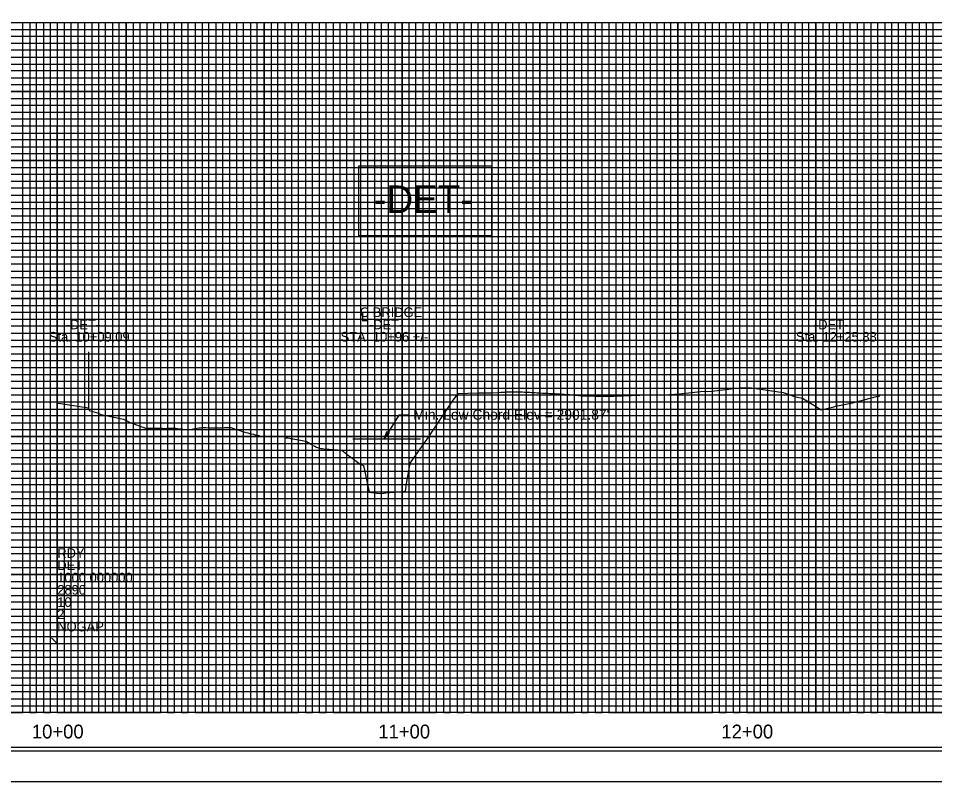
# Model space of a CAD drawing. Extents: x 1191114 to 1192543, y 893004 to 894332.
# Drawn here: x 1191281.1 to 1191546.9, y 893892.3 to 894113.5 of the extents above; entities that cross this region are included whole.
import ezdxf

# ---------------------------------------------------------------- set-up
doc = ezdxf.new("R2010")
doc.units = 0
for name, color, linetype in [('Exist Profile Cell', 7, 'Continuous'), ('Exist Vertical Profile Ground Line', 7, 'Continuous'), ('Prop Grid Mask', 7, 'Continuous'), ('Prop PFL Text', 7, 'Continuous'), ('Prop Vertical Profile Curve Label', 7, 'Continuous'), ('Prop VPI Ditch Grade Right Label', 7, 'Continuous'), ('Sheet Cutting Line CELL', 7, 'Continuous'), ('Sheet DOT Grid CELL', 7, 'Continuous'), ('Sheet Layout Profile Border Port 2', 7, 'Continuous'), ('Sheet Plot Border Inside CELL', 7, 'Continuous'), ('Sheet Plot Border Outside CELL', 7, 'Continuous'), ('Sheet Profile CELL', 7, 'Continuous'), ('Sheet Profile Grid Major CELL', 7, 'Continuous'), ('Sheet Profile Grid Middle CELL', 7, 'Continuous'), ('Sheet Profile Grid Minor CELL', 7, 'Continuous'), ('Typical Terminator CELL', 7, 'Continuous')]:
    doc.layers.add(name, color=color, linetype=linetype)

# ---------------------------------------------------------------- blocks, each defined once
blk = doc.blocks.new('TERMINATOR')
at = {"layer": 'Typical Terminator CELL'}
blk.add_lwpolyline([(-0.469, 0.081), (0, 0), (-0.471, -0.083), (-0.411, 0)], close=True, dxfattribs=at)

msp = doc.modelspace()

# ---------------------------------------------------------------- linework, layer by layer
at = {"layer": 'Exist Profile Cell'}
for q in [(1191292.39, 894082.3), (1191530.97, 893932.3), (1191292.39, 893932.3)]:
    msp.add_line((1191292.39, 893932.3), q, dxfattribs=at)
at = {"layer": 'Exist Vertical Profile Ground Line'}
msp.add_lwpolyline([(1191292.39, 894002.02), (1191293.45, 894001.89), (1191301.48, 894000.69), (1191301.67, 893999.83), (1191304.34, 893999.08), (1191305.07, 893998.7), (1191306.46, 893998.45), (1191311.62, 893997.41), (1191313.53, 893996.39), (1191318, 893994.72), (1191323.03, 893994.72), (1191324.07, 893994.69), (1191324.6, 893994.72), (1191325.12, 893994.74), (1191325.65, 893994.76), (1191326, 893994.78), (1191326.7, 893994.71), (1191327.22, 893994.65), (1191327.75, 893994.6), (1191328.27, 893994.54), (1191328.8, 893994.48), (1191329.32, 893994.41), (1191329.85, 893994.35), (1191330.45, 893994.28), (1191330.9, 893994.36), (1191331.42, 893994.45), (1191331.94, 893994.55), (1191332.47, 893994.64), (1191332.99, 893994.73), (1191333.52, 893994.81), (1191334.04, 893994.89), (1191334.57, 893994.91), (1191335.09, 893994.92), (1191335.48, 893994.93), (1191336.27, 893994.88), (1191336.67, 893994.88), (1191337.19, 893994.88), (1191337.72, 893994.88), (1191338.24, 893994.88), (1191338.77, 893994.88), (1191339.29, 893994.89), (1191339.81, 893994.89), (1191340.34, 893994.89), (1191340.86, 893994.9), (1191341.39, 893994.9), (1191341.91, 893994.9), (1191342.72, 893994.91), (1191343.49, 893994.66), (1191344.01, 893994.49), (1191344.54, 893994.32), (1191345.06, 893994.15), (1191345.59, 893993.99), (1191346.11, 893993.83), (1191346.81, 893993.62), (1191347.16, 893993.52), (1191347.68, 893993.38), (1191348.21, 893993.24), (1191348.73, 893993.11), (1191349.26, 893992.97), (1191349.78, 893992.84), (1191350.31, 893992.71), (1191350.83, 893992.59), (1191351.36, 893992.46), (1191351.71, 893992.38), (1191352.41, 893992.41), (1191352.93, 893992.43), (1191353.57, 893992.45), (1191353.98, 893992.43), (1191354.51, 893992.41), (1191355.03, 893992.39), (1191355.55, 893992.37), (1191356.08, 893992.34), (1191356.6, 893992.32), (1191357.24, 893992.3), (1191357.65, 893992.39), (1191358.18, 893992.39), (1191358.9, 893991.98), (1191359.23, 893991.91), (1191359.75, 893991.81), (1191360.28, 893991.71), (1191360.8, 893991.62), (1191361.33, 893991.52), (1191361.85, 893991.43), (1191362.38, 893991.34), (1191362.9, 893991.25), (1191363.42, 893991.17), (1191363.95, 893991.09), (1191364.56, 893991), (1191365, 893990.72), (1191365.52, 893990.4), (1191366.05, 893990.07), (1191366.61, 893989.73), (1191367.1, 893989.5), (1191367.62, 893989.25), (1191368.15, 893989.04), (1191368.8, 893988.86), (1191369.2, 893988.82), (1191369.72, 893988.76), (1191370.25, 893988.71), (1191370.77, 893988.67), (1191371.29, 893988.63), (1191374.96, 893988.34), (1191376.86, 893986.84), (1191377.41, 893986.48), (1191380.29, 893984.35), (1191381.2, 893983.93), (1191382.87, 893976.17), (1191385.01, 893975.94), (1191386.56, 893975.85), (1191387.64, 893976.03), (1191393.39, 893976.54), (1191393.73, 893978.66), (1191394.73, 893984.58), (1191399.68, 893991.52), (1191407.05, 894002.61), (1191408.65, 894004.79), (1191414.31, 894004.99), (1191418.51, 894005.01), (1191420.2, 894005.1), (1191421.06, 894005.16), (1191421.58, 894005.19), (1191422.1, 894005.23), (1191422.63, 894005.26), (1191423.15, 894005.26), (1191423.67, 894005.26), (1191424.2, 894005.26), (1191424.72, 894005.26), (1191425.24, 894005.26), (1191425.77, 894005.26), (1191426.29, 894005.26), (1191426.81, 894005.26), (1191427.34, 894005.24), (1191427.86, 894005.21), (1191428.38, 894005.19), (1191428.91, 894005.17), (1191429.43, 894005.14), (1191429.95, 894005.11), (1191430.48, 894005.09), (1191431, 894005.06), (1191431.52, 894005.03), (1191432.05, 894005), (1191432.57, 894004.97), (1191433.09, 894004.94), (1191433.62, 894004.91), (1191434.14, 894004.88), (1191434.66, 894004.85), (1191435.19, 894004.82), (1191435.71, 894004.79), (1191436.23, 894004.78), (1191436.76, 894004.76), (1191437.28, 894004.74), (1191437.8, 894004.72), (1191438.33, 894004.68), (1191438.85, 894004.64), (1191439.37, 894004.6), (1191439.9, 894004.55), (1191440.42, 894004.51), (1191440.94, 894004.47), (1191441.47, 894004.42), (1191441.99, 894004.37), (1191442.51, 894004.33), (1191443.04, 894004.28), (1191443.56, 894004.23), (1191444.08, 894004.18), (1191444.61, 894004.13), (1191445.13, 894004.12), (1191445.65, 894004.11), (1191446.18, 894004.11), (1191446.7, 894004.1), (1191447.22, 894004.09), (1191447.75, 894004.08), (1191448.27, 894004.07), (1191451.75, 894003.99), (1191452.85, 894004.03), (1191453.85, 894004.03), (1191461.4, 894004.28), (1191462.86, 894004.37), (1191469.92, 894004.48), (1191472.86, 894004.73), (1191478.98, 894005.35), (1191482.23, 894005.52), (1191490.29, 894006.42), (1191492.08, 894006.51), (1191493.75, 894006.45), (1191502.91, 894005.07), (1191506.54, 894003.82), (1191508.55, 894003.41), (1191512.58, 894000.95), (1191513.9, 894000.04), (1191517.58, 894000.97), (1191518.22, 894001.15), (1191522.99, 894002.06), (1191529.97, 894003.92), (1191530.97, 894004.1)], dxfattribs=at)
at = {"layer": 'Prop Grid Mask'}
msp.add_line((1191292.39, 893932.3), (1191290.73, 893933.97), dxfattribs=at)
msp.add_lwpolyline([(1191379.87, 894070.74), (1191418.35, 894070.74), (1191418.35, 894050.54), (1191379.87, 894050.54)], close=True, dxfattribs=at)
at = {"layer": 'Prop PFL Text'}
for p, q in [((1191391.48, 893998.52), (1191387.16, 893991.65)), ((1191394.4, 893998.52), (1191391.48, 893998.52))]:
    msp.add_line(p, q, dxfattribs=at)
at = {"layer": 'Prop VPI Ditch Grade Right Label'}
for p, q in [((1191301.48, 894016.85), (1191301.48, 894000.69)), ((1191388.39, 894004.75), (1191388.39, 894016.85)), ((1191518.27, 894016.85), (1191518.27, 894001.16)), ((1191378.11, 893991.65), (1191397.79, 893991.65))]:
    msp.add_line(p, q, dxfattribs=at)
at = {"layer": 'Sheet Cutting Line CELL'}
msp.add_line((1191165.59, 893892.3), (1191839.19, 893892.3), dxfattribs=at)
at = {"layer": 'Sheet DOT Grid CELL'}
for p, q in [((1191232.39, 894112.3), (1191832.34, 894112.3)), ((1191292.39, 894112.3), (1191292.39, 893912.3)), ((1191312.39, 894112.3), (1191312.39, 893912.3)), ((1191332.39, 894112.3), (1191332.39, 893912.3)), ((1191352.39, 894112.3), (1191352.39, 893912.3)), ((1191372.39, 894112.3), (1191372.39, 893912.3)), ((1191392.39, 894112.3), (1191392.39, 893912.3)), ((1191412.39, 894112.3), (1191412.39, 893912.3)), ((1191432.39, 894112.3), (1191432.39, 893912.3)), ((1191452.39, 894112.3), (1191452.39, 893912.3)), ((1191472.39, 894112.3), (1191472.39, 893912.3)), ((1191492.39, 894112.3), (1191492.39, 893912.3)), ((1191512.39, 894112.3), (1191512.39, 893912.3)), ((1191532.39, 894112.3), (1191532.39, 893912.3)), ((1191232.39, 894092.3), (1191832.34, 894092.3)), ((1191232.39, 894072.3), (1191832.34, 894072.3)), ((1191232.39, 894052.3), (1191832.34, 894052.3)), ((1191232.39, 894032.3), (1191832.34, 894032.3)), ((1191232.39, 894012.3), (1191832.34, 894012.3)), ((1191232.39, 893992.3), (1191832.34, 893992.3)), ((1191232.39, 893972.3), (1191832.34, 893972.3)), ((1191232.39, 893952.3), (1191832.34, 893952.3)), ((1191232.39, 893932.3), (1191832.34, 893932.3))]:
    msp.add_line(p, q, dxfattribs=at)
at = {"layer": 'Sheet Layout Profile Border Port 2'}
msp.add_lwpolyline([(1191252.39, 894112.3), (1191812.39, 894112.3), (1191812.39, 893912.3), (1191252.39, 893912.3)], close=True, dxfattribs=at)
at = {"layer": 'Sheet Plot Border Inside CELL'}
msp.add_lwpolyline([(1191170.79, 893901.28), (1191837.39, 893901.28), (1191837.39, 894323.32), (1191170.79, 894323.32)], close=True, dxfattribs=at)
at = {"layer": 'Sheet Plot Border Outside CELL'}
msp.add_lwpolyline([(1191165.59, 893892.3), (1191839.19, 893892.3), (1191839.19, 894332.3), (1191165.59, 894332.3)], close=True, dxfattribs=at)
at = {"layer": 'Sheet Profile CELL'}
for p, q in [((1191232.39, 894112.3), (1191832.39, 894112.3)), ((1191832.39, 893912.3), (1191232.39, 893912.3)), ((1191232.39, 893902.3), (1191832.39, 893902.3))]:
    msp.add_line(p, q, dxfattribs=at)
msp.add_lwpolyline([(1191832.39, 894322.3), (1191232.39, 894322.3), (1191232.39, 893902.3), (1191832.39, 893902.3)], close=True, dxfattribs=at)
at = {"layer": 'Sheet Profile Grid Major CELL'}
for p, q in [((1191432.39, 894112.3), (1191452.39, 894112.3)), ((1191472.39, 894112.3), (1191492.39, 894112.3)), ((1191512.39, 894112.3), (1191532.39, 894112.3))]:
    msp.add_line(p, q, dxfattribs=at)
for points in [[(1191272.39, 894112.3), (1191292.39, 894112.3), (1191292.39, 893912.3), (1191312.39, 893912.3), (1191312.39, 894112.3), (1191332.39, 894112.3), (1191332.39, 893912.3), (1191352.39, 893912.3), (1191352.39, 894112.3), (1191372.39, 894112.3), (1191372.39, 893912.3), (1191392.39, 893912.3), (1191392.39, 894112.3), (1191412.39, 894112.3), (1191412.39, 893912.3), (1191432.39, 893912.3), (1191432.39, 894112.3), (1191452.39, 894112.3), (1191452.39, 893912.3), (1191472.39, 893912.3), (1191472.39, 894112.3), (1191492.39, 894112.3), (1191492.39, 893912.3), (1191512.39, 893912.3), (1191512.39, 894112.3), (1191532.39, 894112.3), (1191532.39, 893912.3), (1191552.39, 893912.3)], [(1191832.39, 894092.3), (1191232.39, 894092.3)], [(1191832.39, 894072.3), (1191232.39, 894072.3), (1191232.39, 894052.3), (1191832.39, 894052.3)], [(1191832.39, 894032.3), (1191232.39, 894032.3), (1191232.39, 894012.3), (1191832.39, 894012.3)], [(1191832.39, 893992.3), (1191232.39, 893992.3), (1191232.39, 893972.3), (1191832.39, 893972.3)], [(1191832.39, 893952.3), (1191232.39, 893952.3), (1191232.39, 893952.3), (1191232.39, 893932.3), (1191832.39, 893932.3)], [(1191832.39, 893912.3), (1191232.39, 893912.3)]]:
    msp.add_lwpolyline(points, dxfattribs=at)
at = {"layer": 'Sheet Profile Grid Middle CELL'}
for points in [[(1191262.39, 893912.3), (1191282.39, 893912.3), (1191282.39, 894112.3), (1191302.39, 894112.3), (1191302.39, 893912.3), (1191322.39, 893912.3), (1191322.39, 894112.3), (1191342.39, 894112.3), (1191342.39, 893912.3), (1191362.39, 893912.3), (1191362.39, 894112.3), (1191382.39, 894112.3), (1191382.39, 893912.3), (1191402.39, 893912.3), (1191402.39, 894112.3), (1191422.39, 894112.3), (1191422.39, 893912.3), (1191442.39, 893912.3), (1191442.39, 894112.3), (1191462.39, 894112.3), (1191462.39, 893912.3), (1191482.39, 893912.3), (1191482.39, 893912.3), (1191482.39, 894112.3), (1191502.39, 894112.3), (1191502.39, 893912.3), (1191522.39, 893912.3), (1191522.39, 894112.3), (1191542.39, 894112.3), (1191542.39, 893912.3), (1191562.39, 893912.3)], [(1191232.39, 894102.3), (1191832.39, 894102.3)], [(1191832.39, 894082.3), (1191232.39, 894082.3), (1191232.39, 894062.3), (1191832.39, 894062.3)], [(1191832.39, 894042.3), (1191232.39, 894042.3), (1191232.39, 894022.3), (1191832.39, 894022.3)], [(1191832.39, 894002.3), (1191232.39, 894002.3), (1191232.39, 893982.3), (1191832.39, 893982.3)], [(1191832.39, 893962.3), (1191232.39, 893962.3), (1191232.39, 893942.3), (1191832.39, 893942.3)], [(1191832.39, 893922.3), (1191232.39, 893922.3)]]:
    msp.add_lwpolyline(points, dxfattribs=at)
at = {"layer": 'Sheet Profile Grid Minor CELL'}
for p, q in [((1191252.39, 894110.3), (1191812.39, 894110.3)), ((1191812.39, 894108.3), (1191252.39, 894108.3)), ((1191252.39, 894106.3), (1191812.39, 894106.3)), ((1191812.39, 894104.3), (1191252.39, 894104.3)), ((1191252.39, 894100.3), (1191812.39, 894100.3)), ((1191812.39, 894098.3), (1191252.39, 894098.3)), ((1191252.39, 894096.3), (1191812.39, 894096.3)), ((1191812.39, 894094.3), (1191252.39, 894094.3)), ((1191252.39, 894090.3), (1191812.39, 894090.3)), ((1191812.39, 894088.3), (1191252.39, 894088.3)), ((1191252.39, 894086.3), (1191812.39, 894086.3)), ((1191812.39, 894084.3), (1191252.39, 894084.3)), ((1191252.39, 894080.3), (1191812.39, 894080.3)), ((1191812.39, 894078.3), (1191252.39, 894078.3)), ((1191252.39, 894076.3), (1191812.39, 894076.3)), ((1191812.39, 894074.3), (1191252.39, 894074.3)), ((1191252.39, 894070.3), (1191812.39, 894070.3)), ((1191812.39, 894068.3), (1191252.39, 894068.3)), ((1191252.39, 894066.3), (1191812.39, 894066.3)), ((1191812.39, 894064.3), (1191252.39, 894064.3)), ((1191252.39, 894060.3), (1191812.39, 894060.3)), ((1191812.39, 894058.3), (1191252.39, 894058.3)), ((1191252.39, 894056.3), (1191812.39, 894056.3)), ((1191812.39, 894054.3), (1191252.39, 894054.3)), ((1191252.39, 894050.3), (1191812.39, 894050.3)), ((1191812.39, 894048.3), (1191252.39, 894048.3)), ((1191252.39, 894046.3), (1191812.39, 894046.3)), ((1191812.39, 894044.3), (1191252.39, 894044.3)), ((1191252.39, 894040.3), (1191812.39, 894040.3)), ((1191812.39, 894038.3), (1191252.39, 894038.3)), ((1191252.39, 894036.3), (1191812.39, 894036.3)), ((1191812.39, 894034.3), (1191252.39, 894034.36)), ((1191252.39, 894030.3), (1191812.39, 894030.3)), ((1191812.39, 894028.3), (1191252.39, 894028.3)), ((1191252.39, 894026.3), (1191812.39, 894026.3)), ((1191812.39, 894024.3), (1191252.39, 894024.3)), ((1191252.39, 894020.3), (1191812.39, 894020.3)), ((1191812.39, 894018.3), (1191252.39, 894018.3)), ((1191252.39, 894016.3), (1191812.39, 894016.3)), ((1191812.39, 894014.3), (1191252.39, 894014.3)), ((1191252.39, 894010.3), (1191812.39, 894010.3)), ((1191812.39, 894008.3), (1191252.39, 894008.3)), ((1191252.39, 894006.3), (1191812.39, 894006.3)), ((1191812.39, 894004.3), (1191252.39, 894004.3)), ((1191252.39, 894000.3), (1191812.39, 894000.3)), ((1191812.39, 893998.3), (1191252.39, 893998.3)), ((1191252.39, 893996.3), (1191812.39, 893996.3)), ((1191812.39, 893994.3), (1191252.39, 893994.3)), ((1191252.39, 893990.3), (1191812.39, 893990.3)), ((1191812.39, 893988.3), (1191252.39, 893988.3)), ((1191252.39, 893986.3), (1191812.39, 893986.3)), ((1191812.39, 893984.3), (1191252.39, 893984.3)), ((1191252.39, 893980.3), (1191812.39, 893980.3)), ((1191812.39, 893978.3), (1191252.39, 893978.3)), ((1191252.39, 893976.3), (1191812.39, 893976.3)), ((1191812.39, 893974.3), (1191252.39, 893974.3)), ((1191252.39, 893970.3), (1191812.39, 893970.3)), ((1191812.39, 893968.3), (1191252.39, 893968.3)), ((1191252.39, 893966.3), (1191812.39, 893966.3)), ((1191812.39, 893964.3), (1191252.39, 893964.3)), ((1191252.39, 893960.3), (1191812.39, 893960.3)), ((1191812.39, 893958.3), (1191252.39, 893958.3)), ((1191252.39, 893956.3), (1191812.39, 893956.3)), ((1191812.39, 893954.3), (1191252.39, 893954.3)), ((1191252.39, 893950.3), (1191812.39, 893950.3)), ((1191812.39, 893948.3), (1191252.39, 893948.3)), ((1191252.39, 893946.3), (1191812.39, 893946.3)), ((1191812.39, 893944.3), (1191252.39, 893944.3)), ((1191252.39, 893940.3), (1191812.39, 893940.3)), ((1191812.39, 893938.3), (1191252.39, 893938.3)), ((1191252.39, 893936.3), (1191812.39, 893936.3)), ((1191812.39, 893934.3), (1191252.39, 893934.3)), ((1191252.39, 893930.3), (1191812.39, 893930.3)), ((1191812.39, 893928.3), (1191252.39, 893928.3)), ((1191252.39, 893926.3), (1191812.39, 893926.3)), ((1191812.39, 893924.3), (1191252.39, 893924.3)), ((1191252.39, 893920.3), (1191812.39, 893920.3)), ((1191812.39, 893918.3), (1191252.39, 893918.3)), ((1191252.39, 893916.3), (1191812.39, 893916.3)), ((1191252.39, 893914.3), (1191812.39, 893914.3))]:
    msp.add_line(p, q, dxfattribs=at)
for points in [[(1191280.39, 894112.3), (1191284.39, 894112.3), (1191284.39, 893912.3), (1191286.39, 893912.3), (1191286.39, 894112.3), (1191288.39, 894112.3), (1191288.39, 893912.3), (1191290.39, 893912.3), (1191290.39, 894112.3), (1191294.39, 894112.3), (1191294.39, 893912.3), (1191296.39, 893912.3), (1191296.39, 894112.3), (1191298.39, 894112.3), (1191298.39, 893912.3), (1191300.39, 893912.3), (1191300.39, 894112.3), (1191304.39, 894112.3), (1191304.39, 893912.3), (1191306.39, 893912.3), (1191306.39, 894112.3), (1191308.39, 894112.3), (1191308.39, 893912.3), (1191310.39, 893912.3), (1191310.39, 894112.3), (1191314.39, 894112.3), (1191314.39, 893912.3), (1191316.39, 893912.3), (1191316.39, 894112.3), (1191318.39, 894112.3), (1191318.39, 893912.3), (1191320.39, 893912.3), (1191320.39, 894112.3), (1191324.39, 894112.3), (1191324.39, 893912.3), (1191326.39, 893912.3), (1191326.39, 894112.3), (1191328.39, 894112.3), (1191328.39, 893912.3), (1191330.39, 893912.3), (1191330.39, 894112.3), (1191334.39, 894112.3), (1191334.39, 893912.3), (1191336.39, 893912.3), (1191336.39, 894112.3), (1191338.39, 894112.3), (1191338.39, 893912.3)], [(1191338.39, 893912.3), (1191340.39, 893912.3), (1191340.39, 894112.3), (1191344.39, 894112.3), (1191344.39, 893912.3), (1191346.39, 893912.3), (1191346.39, 894112.3), (1191348.39, 894112.3), (1191348.39, 893912.3), (1191350.39, 893912.3), (1191350.39, 894112.3), (1191354.39, 894112.3), (1191354.39, 893912.3), (1191356.39, 893912.3), (1191356.39, 894112.3), (1191358.39, 894112.3), (1191358.39, 893912.3), (1191360.39, 893912.3), (1191360.39, 894112.3), (1191364.39, 894112.3), (1191364.39, 893912.3), (1191366.39, 893912.3), (1191366.39, 894112.3), (1191368.39, 894112.3), (1191368.39, 893912.3), (1191370.39, 893912.3), (1191370.39, 894112.3), (1191374.39, 894112.3), (1191374.39, 893912.3), (1191376.39, 893912.3), (1191376.39, 894112.3), (1191378.39, 894112.3), (1191378.39, 893912.3), (1191380.39, 893912.3), (1191380.39, 894112.3), (1191384.39, 894112.3), (1191384.39, 893912.3), (1191386.39, 893912.3), (1191386.39, 894112.3), (1191388.39, 894112.3), (1191388.39, 893912.3), (1191390.39, 893912.3), (1191390.39, 894112.3), (1191394.39, 894112.3), (1191394.39, 893912.3), (1191396.39, 893912.3), (1191396.39, 894112.3), (1191398.39, 894112.3), (1191398.39, 893912.3), (1191400.39, 893912.3), (1191400.39, 894112.3), (1191404.39, 894112.3), (1191404.39, 893912.3), (1191406.39, 893912.3), (1191406.39, 894112.3), (1191408.39, 894112.3), (1191408.39, 893912.3), (1191410.39, 893912.3), (1191410.39, 894112.3), (1191414.39, 894112.3), (1191414.39, 893912.3), (1191416.39, 893912.3), (1191416.39, 894112.3), (1191418.39, 894112.3), (1191418.39, 893912.3), (1191420.39, 893912.3), (1191420.39, 894112.3), (1191424.39, 894112.3), (1191424.39, 893912.3), (1191426.39, 893912.3), (1191426.39, 894112.3), (1191428.39, 894112.3), (1191428.39, 893912.3), (1191430.39, 893912.3), (1191430.39, 894112.3), (1191434.39, 894112.3), (1191434.39, 893912.3), (1191436.39, 893912.3), (1191436.39, 894112.3), (1191438.39, 894112.3), (1191438.39, 893912.3), (1191440.39, 893912.3), (1191440.39, 894112.3), (1191444.39, 894112.3), (1191444.39, 893912.3), (1191446.39, 893912.3), (1191446.39, 894112.3), (1191448.39, 894112.3), (1191448.39, 893912.3), (1191450.39, 893912.3), (1191450.39, 894112.3), (1191454.39, 894112.3), (1191454.39, 893912.3), (1191456.39, 893912.3), (1191456.39, 894112.3), (1191458.39, 894112.3), (1191458.39, 893912.3), (1191460.39, 893912.3), (1191460.39, 894112.3), (1191464.39, 894112.3)], [(1191464.39, 894112.3), (1191464.39, 893912.3), (1191466.39, 893912.3), (1191466.39, 894112.3), (1191468.39, 894112.3), (1191468.39, 893912.3), (1191470.39, 893912.3), (1191470.39, 894112.3), (1191474.39, 894112.3), (1191474.39, 893912.3), (1191476.39, 893912.3), (1191476.39, 894112.3), (1191478.39, 894112.3), (1191478.39, 893912.3), (1191480.39, 893912.3), (1191480.39, 894112.3), (1191484.39, 894112.3), (1191484.39, 893912.3), (1191486.39, 893912.3), (1191486.39, 894112.3), (1191488.39, 894112.3), (1191488.39, 893912.3), (1191490.39, 893912.3), (1191490.39, 894112.3), (1191494.39, 894112.3), (1191494.39, 893912.3), (1191496.39, 893912.3), (1191496.39, 894112.3), (1191498.39, 894112.3), (1191498.39, 893912.3), (1191500.39, 893912.3), (1191500.39, 894112.3), (1191504.39, 894112.3), (1191504.39, 893912.3), (1191506.39, 893912.3), (1191506.39, 894112.3), (1191508.39, 894112.3), (1191508.39, 893912.3), (1191510.39, 893912.3), (1191510.39, 894112.3), (1191514.39, 894112.3), (1191514.39, 893912.3), (1191514.39, 893912.3), (1191516.39, 893912.3), (1191516.39, 894112.3), (1191518.39, 894112.3), (1191518.39, 893912.3), (1191520.39, 893912.3), (1191520.39, 894112.3), (1191524.39, 894112.3), (1191524.39, 893912.3), (1191526.39, 893912.3), (1191526.39, 894112.3), (1191528.39, 894112.3), (1191528.39, 893912.3), (1191530.39, 893912.3), (1191530.39, 894112.3), (1191534.39, 894112.3), (1191534.39, 893912.3), (1191536.39, 893912.3), (1191536.39, 894112.3), (1191538.39, 894112.3), (1191538.39, 893912.3), (1191540.39, 893912.3), (1191540.39, 894112.3), (1191544.39, 894112.3), (1191544.39, 893912.3), (1191546.39, 893912.3), (1191546.39, 894112.3), (1191548.39, 894112.3)]]:
    msp.add_lwpolyline(points, dxfattribs=at)

# ---------------------------------------------------------------- block references
at = {"layer": 'Prop PFL Text', "xscale": 4.999999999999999, "yscale": 5, "rotation": -122.16722662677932}
msp.add_blockref('TERMINATOR', (1191387.16, 893991.65), dxfattribs=at)
msp.add_blockref('TERMINATOR', (1191387.16, 893991.65), dxfattribs=at)

# ---------------------------------------------------------------- texts
at = {"layer": 'Exist Profile Cell'}
for s, p in [('RDY', (1191292.39, 893957.15)), ('DET', (1191292.39, 893953.6)), ('1000.000000', (1191292.39, 893950.05)), ('2890', (1191292.39, 893946.5)), ('10', (1191292.39, 893942.95)), ('2', (1191292.39, 893939.4)), ('NOGAP', (1191292.39, 893935.85))]:
    msp.add_text(s, height=2.8, dxfattribs=at).set_placement(p)
at = {"layer": 'Exist Vertical Profile Ground Line'}
for s, p in [('10+00', (1191285.02, 893904.83)), ('11+00', (1191385.5, 893904.83)), ('12+00', (1191485.01, 893904.83))]:
    msp.add_text(s, height=4, dxfattribs=at).set_placement(p)
at = {"layer": 'Prop PFL Text'}
msp.add_text("Min. Low Chord Elev = 2901.87'", height=3, dxfattribs=at).set_placement((1191395.64, 893997.19))
at = {"layer": 'Prop Vertical Profile Curve Label'}
msp.add_text('-DET-', height=8, rotation=360, dxfattribs=at).set_placement((1191384.3, 894057.1))
at = {"layer": 'Prop VPI Ditch Grade Right Label'}
for s, p in [('C BRIDGE', (1191380.15, 894026.95)), ('L', (1191380.46, 894025.75)), ('-DET-', (1191294.87, 894023.4)), ('-DET-', (1191382.79, 894023.4)), ('-DET-', (1191511.84, 894023.4)), ('Sta. 10+09.09', (1191289.96, 894019.85)), ('STA. 10+96 +/-', (1191374.57, 894019.85)), ('Sta. 12+25.88', (1191506.63, 894019.85))]:
    msp.add_text(s, height=2.8, dxfattribs=at).set_placement(p)

doc.saveas('drawing.dxf')
